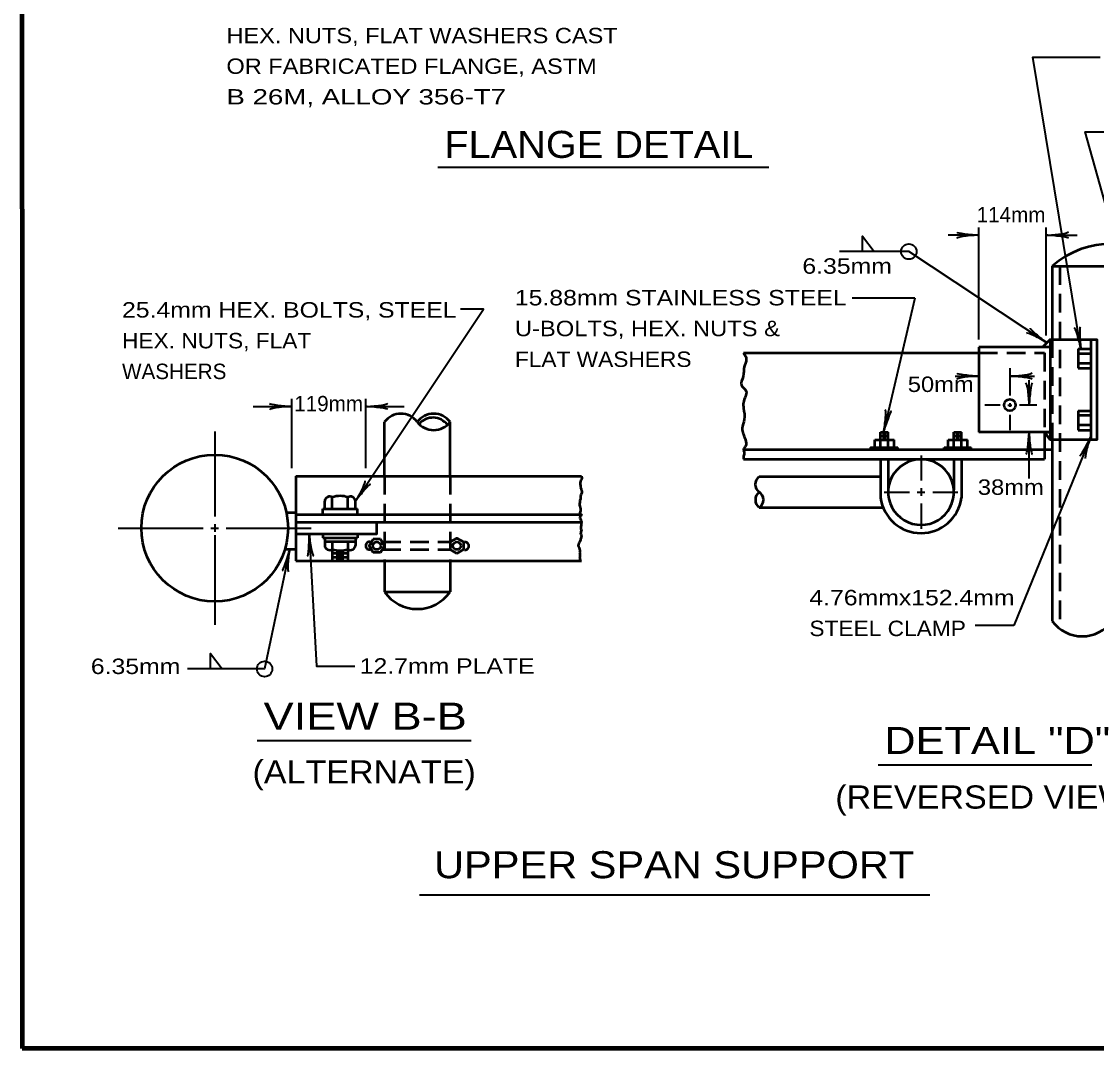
# Model space of a CAD drawing. Extents: x -29 to 827, y -14 to 530.
# Drawn here: x 28.3 to 196.8, y -2.8 to 158 of the extents above; entities that cross this region are included whole.
import ezdxf

# ---------------------------------------------------------------- set-up
doc = ezdxf.new("R2010")
doc.units = 0
doc.header["$LTSCALE"] = 0.97
doc.linetypes.add('MEDIUM_DASHED', pattern=[4.5, 3, -1.5])
doc.layers.add('1', color=7, linetype='Continuous', lineweight=53)

msp = doc.modelspace()

# ---------------------------------------------------------------- linework, layer by layer
at = {"layer": '1', "lineweight": 40}
for p, q in [((93.5745, 135.1797), (145.4625, 135.1797)), ((65.2914, 45.3846), (98.7954, 45.3846)), ((162.5634, 41.5926), (196.0674, 41.5926)), ((90.6859, 21.2275), (170.6693, 21.2275))]:
    msp.add_line(p, q, dxfattribs=at)
at = {"layer": '1', "lineweight": 35}
for p, q in [((178.3794, 108.2166), (178.3794, 125.7366)), ((188.9394, 108.8406), (188.9394, 125.7366)), ((178.3794, 124.5366), (173.5554, 124.5366)), ((188.9394, 124.5366), (193.7634, 124.5366)), ((167.4114, 121.9686), (156.5154, 121.9686)), ((189.0354, 107.6646), (167.4114, 121.9686)), ((168.3474, 114.6486), (158.4989, 114.6486)), ((168.3474, 114.6486), (163.4034, 93.6966)), ((183.2274, 103.6806), (183.2274, 99.4326)), ((174.6594, 102.4566), (178.3794, 102.4566)), ((183.2274, 102.4566), (187.0674, 102.4566)), ((186.2514, 97.9206), (186.2514, 101.8326)), ((70.7154, 88.0326), (70.7154, 98.9046)), ((82.2834, 88.0326), (82.2834, 98.9046)), ((181.7154, 97.9206), (179.2914, 97.9206)), ((182.9154, 97.9206), (183.5154, 97.9206)), ((183.2274, 98.2326), (183.2274, 97.6326)), ((187.4514, 97.9206), (184.7394, 97.9206)), ((64.6674, 97.7046), (70.7154, 97.7046)), ((82.2834, 97.7046), (88.3314, 97.7046)), ((183.2274, 96.4086), (183.2274, 93.9846)), ((58.6194, 93.7686), (58.6194, 80.4726)), ((195.9234, 93.0006), (183.8274, 63.4086)), ((186.2514, 86.4246), (186.2514, 93.6966)), ((169.3074, 90.0486), (169.3074, 86.1126)), ((163.5474, 84.2886), (167.5074, 84.2886)), ((168.7074, 84.2886), (169.9074, 84.2886)), ((169.3074, 84.8886), (169.3074, 83.6886)), ((171.1314, 84.2886), (175.0674, 84.2886)), ((169.3074, 82.4886), (169.3074, 78.5526)), ((43.4994, 78.6486), (56.7954, 78.6486)), ((58.0194, 78.6486), (58.6194, 78.6486)), ((58.6194, 78.6486), (58.6194, 78.0486)), ((58.6194, 77.5686), (58.6194, 63.5286)), ((60.4194, 78.6486), (73.7394, 78.6486)), ((183.8274, 63.4086), (177.7794, 63.4086))]:
    msp.add_line(p, q, dxfattribs=at)
at = {"layer": '1'}
for p, q in [((189.8754, 119.6886), (208.6194, 119.6886)), ((189.8754, 119.6886), (189.8754, 108.2166)), ((189.5634, 108.2166), (188.3634, 106.9926)), ((189.5634, 108.2166), (189.5634, 92.4726)), ((195.9234, 108.2166), (195.9234, 92.4726)), ((178.3794, 106.9926), (178.3794, 93.6966)), ((189.5634, 106.9926), (178.3794, 106.9926)), ((193.9554, 106.7046), (193.9554, 103.6806)), ((193.9554, 106.7046), (195.9234, 106.7046)), ((141.4914, 106.0806), (178.3794, 106.0806)), ((195.9234, 105.9366), (193.9554, 105.9366)), ((195.9234, 104.4246), (193.9554, 104.4246)), ((193.9554, 103.6806), (195.9234, 103.6806)), ((193.9554, 97.0086), (193.9554, 93.9846)), ((193.9554, 97.0086), (195.9234, 97.0086)), ((195.9234, 96.2646), (193.9554, 96.2646)), ((85.2354, 86.8086), (85.2354, 95.2806)), ((95.5074, 86.8086), (95.5074, 95.2806)), ((195.9234, 94.7526), (193.9554, 94.7526)), ((162.9714, 91.2726), (162.9714, 93.6966)), ((162.9714, 93.6966), (164.1714, 93.6966)), ((162.9714, 93.0966), (164.1714, 93.0966)), ((163.2594, 93.3846), (163.8594, 93.3846)), ((163.2594, 92.7846), (163.8594, 92.7846)), ((164.1714, 91.2726), (164.1714, 93.6966)), ((174.4434, 91.2726), (174.4434, 93.6966)), ((174.4434, 93.6966), (175.6674, 93.6966)), ((174.4434, 93.0966), (175.6674, 93.0966)), ((174.7554, 93.3846), (175.3554, 93.3846)), ((174.7554, 92.7846), (175.3554, 92.7846)), ((175.6674, 91.2726), (175.6674, 93.6966)), ((189.5634, 93.6966), (178.3794, 93.6966)), ((188.6754, 93.6966), (188.6754, 89.4486)), ((188.6754, 93.6966), (189.5634, 92.4726)), ((193.9554, 93.9846), (195.9234, 93.9846)), ((162.0594, 91.2726), (162.0594, 92.4726)), ((162.0594, 92.4726), (165.0834, 92.4726)), ((165.0834, 91.2726), (165.0834, 92.4726)), ((165.6834, 90.9606), (165.6834, 91.2726)), ((172.9314, 90.9606), (172.9314, 91.2726)), ((172.9314, 91.2726), (177.1794, 91.2726)), ((173.5554, 91.2726), (173.5554, 92.4726)), ((173.5554, 92.4726), (176.5794, 92.4726)), ((176.5794, 91.2726), (176.5794, 92.4726)), ((177.1794, 90.9606), (177.1794, 91.2726)), ((189.8754, 92.4726), (189.8754, 64.0566)), ((141.4914, 90.9606), (189.8754, 90.9606)), ((162.9714, 89.4486), (162.9714, 83.4006)), ((164.1714, 89.4486), (164.1714, 84.6246)), ((174.4434, 89.4486), (174.4434, 84.6246)), ((175.6674, 89.4486), (175.6674, 83.4006)), ((71.3154, 86.8086), (116.0754, 86.8086)), ((71.3154, 86.8086), (71.3154, 73.5126)), ((143.9154, 86.7126), (162.9714, 86.7126)), ((75.8514, 81.6726), (75.8514, 82.8966)), ((77.0514, 81.6726), (77.0514, 83.4966)), ((79.4754, 81.6726), (79.4754, 83.4966)), ((80.6994, 81.6726), (80.6994, 82.8966)), ((69.8514, 81.0726), (71.3154, 81.0726)), ((75.5394, 80.7606), (75.5394, 81.6726)), ((75.5394, 81.6726), (80.9874, 81.6726)), ((80.9874, 80.7606), (80.9874, 81.6726)), ((143.9154, 81.8646), (163.3794, 81.8646)), ((71.3154, 80.7606), (116.0754, 80.7606)), ((71.3154, 79.5606), (116.0754, 79.5606)), ((75.5394, 77.7366), (75.5394, 77.1366)), ((80.9874, 77.7366), (80.9874, 77.1366)), ((75.5394, 77.1366), (80.9874, 77.1366)), ((75.8514, 77.1366), (75.8514, 75.9366)), ((75.8514, 76.5366), (80.6994, 76.5366)), ((77.0514, 76.5366), (77.0514, 73.5126)), ((79.4754, 76.5366), (79.4754, 73.5126)), ((80.6994, 77.1366), (80.6994, 75.9366)), ((84.6114, 76.9446), (83.4354, 76.9446)), ((95.5074, 76.4886), (95.5074, 75.2886)), ((97.6194, 76.4886), (97.6194, 75.2886)), ((69.6114, 75.3366), (71.3154, 75.3366)), ((77.0514, 74.7126), (79.4754, 74.7126)), ((77.6754, 75.0246), (78.8754, 75.0246)), ((77.6754, 74.4246), (78.8754, 74.4246)), ((84.6114, 74.8326), (83.4354, 74.8326)), ((96.5634, 74.6886), (95.5074, 75.2886)), ((97.6194, 75.2886), (96.5634, 74.6886)), ((71.3154, 73.5126), (116.0754, 73.5126)), ((77.0514, 74.1126), (79.4754, 74.1126)), ((77.6754, 73.8246), (78.8754, 73.8246)), ((85.2354, 73.5126), (85.2354, 68.6646)), ((95.5074, 73.5126), (95.5074, 68.6646)), ((85.2354, 68.6646), (95.5074, 68.6646))]:
    msp.add_line(p, q, dxfattribs=at)
at = {"layer": '1', "linetype": 'MEDIUM_DASHED'}
for p, q in [((191.0754, 119.6886), (191.0754, 62.8566)), ((189.8754, 108.2166), (189.8754, 92.4726)), ((85.2354, 86.8086), (85.2354, 73.5126)), ((95.5074, 86.8086), (95.5074, 73.5126)), ((84.8754, 76.4886), (95.5074, 76.4886)), ((84.8754, 75.2886), (95.5074, 75.2886))]:
    msp.add_line(p, q, dxfattribs=at)
at = {"layer": '1', "lineweight": 158}
msp.add_line((820.0407, -2.8455), (28.4407, -2.8455), dxfattribs=at)
msp.add_lwpolyline([(820.0407, 523.2545), (28.3407, 523.1545), (28.4407, -2.8455)], dxfattribs=at)
at = {"layer": '1', "lineweight": 35}
for points in [[(194.3533, 106.7046), (186.8294, 152.4004), (197.3654, 152.4004)], [(203.1234, 111.8406), (195.0114, 140.7126), (205.5474, 140.7126)], [(160.1394, 121.9686), (160.1394, 124.3686), (161.9634, 121.9686)], [(80.6994, 82.8966), (100.7394, 112.9446), (97.1522, 112.9446)], [(58.6194, 79.2486), (58.6194, 78.6486), (59.2194, 78.6486)], [(73.4274, 77.7366), (74.5554, 57.0246), (80.6034, 57.0246)], [(70.3794, 75.3366), (66.4434, 56.5926), (54.3474, 56.5926)], [(57.9714, 56.5926), (57.9714, 59.0166), (59.7714, 56.5926)]]:
    msp.add_lwpolyline(points, dxfattribs=at)
at = {"layer": '1'}
for points in [[(188.3634, 106.9926), (189.5634, 108.2166), (189.5634, 106.9926)], [(189.5634, 92.4726), (188.6754, 93.6966), (189.5634, 93.6966)]]:
    msp.add_lwpolyline(points, close=True, dxfattribs=at)
for points in [[(189.5634, 108.2166), (196.8354, 108.2166), (196.8354, 92.4726), (189.5634, 92.4726)], [(161.4594, 90.9606), (161.4594, 91.2726), (165.6834, 91.2726)], [(141.4914, 89.4486), (164.1714, 89.4486), (174.4434, 89.4486), (188.6754, 89.4486)], [(71.3154, 77.7366), (84.0114, 77.7366), (84.0114, 79.5606)], [(83.4354, 74.8326), (82.8114, 75.8886), (83.4354, 76.9446)], [(84.6114, 76.9446), (85.2354, 75.8886), (84.6114, 74.8326)], [(95.5074, 76.4886), (96.5634, 77.0886), (97.6194, 76.4886)]]:
    msp.add_lwpolyline(points, dxfattribs=at)
at = {"layer": '1', "linetype": 'MEDIUM_DASHED'}
msp.add_lwpolyline([(178.3794, 106.0806), (188.6754, 106.0806), (188.6754, 93.6966)], dxfattribs=at)
at = {"layer": '1', "lineweight": 35}
for centre in [(167.4011, 121.9584), (66.4358, 56.5906)]:
    msp.add_circle(centre, 1.2096, dxfattribs=at)
at = {"layer": '1'}
for centre, radius in [((183.2249, 97.9252), 0.9072), ((58.6144, 78.6518), 11.4912), ((84.023, 75.8857), 0.6048), ((96.5656, 75.8857), 0.6048)]:
    msp.add_circle(centre, radius, dxfattribs=at)
for centre, radius, start, end in [((199.2521, 108.8867), 14.3095, 49.07159, 130.92841), ((87.796, 93.3356), 3.2253, 37.16004, 142.83996), ((92.9368, 93.3356), 3.2253, 37.16004, 142.83996), ((92.9368, 97.2321), 3.2253, 217.16004, 322.83996), ((92.831, 93.1726), 2.7851, 36.24736, 140.76859), ((169.3145, 84.2854), 5.1509, 356.40861, 183.59139), ((144.8528, 85.5008), 1.5318, 127.84869, 232.15131), ((144.91, 83.0816), 1.5676, 129.50016, 230.49985), ((143.1247, 83.0816), 1.4728, 304.78683, 56.54264), ((169.3145, 84.2969), 5.1509, 176.40861, 3.59139), ((76.6486, 82.8026), 0.8017, 59.06287, 174.06723), ((78.2704, 79.9306), 3.7595, 71.23152, 108.76847), ((79.8921, 82.8026), 0.8017, 5.93277, 120.93713), ((169.3145, 84.2729), 6.4088, 187.73761, 352.26239), ((76.6486, 76.0131), 0.8017, 185.93277, 300.93712), ((79.8921, 76.0131), 0.8017, 239.06287, 354.06723), ((82.8801, 75.8857), 0.6024, 82.89428, 277.10571), ((97.8541, 75.8598), 0.6024, 262.89429, 97.10572), ((78.2704, 78.885), 3.7595, 251.23153, 288.76848), ((90.3664, 72.2544), 6.2656, 214.86649, 325.13351), ((194.5649, 67.5743), 5.8605, 216.88967, 323.11034)]:
    msp.add_arc(centre, radius, start, end, dxfattribs=at)
at = {"layer": '1', "lineweight": 40}
for centre, major_axis, ratio, start_param, end_param in [((177.0312, 124.7923), (2.1246, -0.2125), 0.07063, 3.14071475, 5.41810995), ((190.2518, 124.8706), (-2.16, -0.1889), 0.122415, 0.89635335, 3.14159265), ((190.2518, 124.8706), (-2.16, -0.1889), 0.122415, 0.89635335, 3.14159265), ((177.0666, 124.2022), (2.16, 0.1889), 0.122415, 0.89635335, 3.14159265), ((190.2873, 124.2804), (-2.1246, 0.2125), 0.07063, 3.14071475, 5.41810995), ((190.2873, 124.2804), (-2.1246, 0.2125), 0.07063, 3.14071475, 5.41810995), ((188.0503, 108.6322), (-1.656, 1.3479), 0.07063, 6.28230741, 8.55970261), ((193.8134, 107.9428), (0.533, -2.0839), 0.122415, 0.89635335, 3.14159265), ((194.3854, 108.0726), (0.1345, -2.114), 0.07063, 3.14071475, 5.41810995), ((187.7547, 108.1202), (1.9066, -1.0325), 0.122415, 0.89635335, 3.14159265), ((177.0312, 102.7171), (2.1246, -0.2125), 0.07063, 3.14071475, 5.41810995), ((184.5448, 102.7954), (-2.16, -0.1889), 0.122415, 0.89635335, 3.14159265), ((184.5448, 102.7954), (-2.16, -0.1889), 0.122415, 0.89635335, 3.14159265), ((177.0666, 102.127), (2.16, 0.1889), 0.122415, 0.89635335, 3.14159265), ((184.5803, 102.2052), (-2.1246, 0.2125), 0.07063, 3.14071475, 5.41810995), ((184.5803, 102.2052), (-2.1246, 0.2125), 0.07063, 3.14071475, 5.41810995), ((185.9147, 99.2451), (0.1889, -2.16), 0.122415, 0.89635335, 3.14159265), ((186.5049, 99.2806), (-0.2125, -2.1246), 0.07063, 3.14071475, 5.41810995), ((69.3553, 97.959), (2.1246, -0.2125), 0.07063, 3.14071475, 5.41810995), ((69.3553, 97.959), (2.1246, -0.2125), 0.07063, 3.14071475, 5.41810995), ((83.6023, 98.0372), (-2.16, -0.1889), 0.122415, 0.89635335, 3.14159265), ((69.3907, 97.3688), (2.16, 0.1889), 0.122415, 0.89635335, 3.14159265), ((69.3907, 97.3688), (2.16, 0.1889), 0.122415, 0.89635335, 3.14159265), ((83.6377, 97.4471), (-2.1246, 0.2125), 0.07063, 3.14071475, 5.41810995), ((163.3889, 95.053), (-0.3112, -2.1458), 0.122415, 0.89635335, 3.14159265), ((163.9715, 94.9522), (0.6938, 2.0194), 0.07063, 6.28230741, 8.55970261), ((185.993, 92.3362), (0.2125, 2.1246), 0.07063, 3.14071475, 5.41810995), ((186.5831, 92.3717), (-0.1889, 2.16), 0.122415, 0.89635335, 3.14159265), ((195.1755, 91.8368), (-1.0013, -1.8859), 0.07063, 6.28230741, 8.55970261), ((195.7351, 91.6461), (0.6433, 2.0706), 0.122415, 0.89635335, 3.14159265), ((81.1441, 84.1689), (-1.0416, -1.9016), 0.122415, 0.89635335, 3.14159265), ((81.6547, 83.8708), (1.3559, 1.6495), 0.07063, 6.28230741, 8.55970261), ((73.2489, 76.3774), (-0.0965, -2.133), 0.07063, 6.28230741, 8.55970261), ((73.8362, 76.4449), (-0.3062, 2.1465), 0.122415, 0.89635335, 3.14159265), ((69.8529, 74.052), (-0.6459, -2.0352), 0.07063, 6.28230741, 8.55970261), ((70.4377, 73.965), (0.2605, 2.1525), 0.122415, 0.89635335, 3.14159265)]:
    msp.add_ellipse(centre, major_axis=major_axis, ratio=ratio, start_param=start_param, end_param=end_param, dxfattribs=at)
at = {"layer": '1'}
for points in [[(141.4914, 106.0806), (141.9234, 105.0726), (141.5874, 103.9206), (141.4434, 102.4086), (141.1554, 101.0166), (141.8994, 100.1046), (141.8034, 99.2886), (141.4674, 98.3046), (141.4914, 97.4406), (141.6114, 95.6646), (141.2754, 94.2726), (141.4434, 93.4326), (141.7794, 92.4726), (141.8034, 91.4886), (141.4914, 90.9606), (141.6114, 90.4086), (141.4674, 89.7606), (141.4914, 89.4486)], [(116.0754, 86.8086), (116.0994, 86.3286), (115.9794, 86.1366), (115.9074, 85.7766), (115.9314, 85.2966), (116.0274, 84.7686), (116.1474, 84.2886), (116.0994, 84.0486), (115.9554, 83.6406), (115.9554, 83.3766), (115.9314, 83.2326), (115.8354, 82.9686), (115.8114, 82.6566), (115.7874, 82.3926), (115.7874, 82.2486), (115.8834, 81.8886), (115.9554, 81.4806), (115.9074, 81.1926), (115.8594, 80.9526), (116.0754, 80.7606), (115.8354, 80.3046), (115.8834, 80.1606), (116.0034, 79.9926), (116.0034, 79.8246), (116.0754, 79.6086), (116.0754, 79.5606), (115.9794, 78.6246), (115.9794, 78.5526), (116.0754, 78.2646), (116.0034, 78.0486), (115.9554, 77.8566), (116.0274, 77.5926), (116.0754, 77.3766), (115.9554, 76.9446), (115.8834, 76.6566), (115.6914, 76.2726), (115.5954, 75.9126), (115.7154, 75.5526), (115.8114, 75.1206), (115.8114, 74.9526), (115.8114, 74.7126), (115.8354, 74.4006), (115.8114, 74.2086), (115.8114, 74.0406), (115.8354, 73.8246), (115.8114, 73.6566), (116.0754, 73.5126)]]:
    msp.add_spline(points, degree=3, dxfattribs=at)

# ---------------------------------------------------------------- texts
for s, height, width, p in [('HEX. NUTS, FLAT WASHERS CAST', 2.4, 1.15, (60.4538, 154.5991)), ('OR FABRICATED FLANGE, ASTM', 2.4, 1.15, (60.4538, 149.7991)), ('B 26M, ALLOY 356-T7 ', 2.4, 1.35, (60.4538, 144.9991)), ('FLANGE DETAIL', 4.234, 1.1, (94.5923, 136.634)), ('6.35mm', 2.419, 1.2, (150.7135, 118.4908)), ('15.88mm STAINLESS STEEL', 2.419, 1.2, (105.6583, 113.5317)), ('25.4mm HEX. BOLTS, STEEL', 2.419, 1.2, (44.0958, 111.6246)), ('U-BOLTS, HEX. NUTS &', 2.419, 1.15, (105.6583, 108.7125)), ('HEX. NUTS, FLAT', 2.419, 1.1, (44.0958, 106.8054)), ('FLAT WASHERS', 2.419, 1.1, (105.6583, 103.8933)), ('50mm', 2.419, 1.15, (167.2271, 99.9726)), ('38mm', 2.419, 1.15, (178.2102, 83.8638)), ('4.76mmx152.4mm', 2.419, 1.2, (151.8114, 66.5574)), ('STEEL CLAMP', 2.419, 1.1, (151.8114, 61.7382)), ('6.35mm', 2.419, 1.2, (39.2083, 55.7982)), ('12.7mm PLATE', 2.419, 1.2, (81.3474, 55.8486)), ('VIEW B-B', 4.234, 1.25, (66.2754, 47.0886)), ('DETAIL "D"', 4.234, 1.2, (163.5474, 43.2726)), ('(ALTERNATE)', 3.629, 1.1, (64.539, 38.6644)), ('(REVERSED VIEW)', 3.629, 1.1, (155.8712, 34.7247)), ('UPPER SPAN SUPPORT', 4.234, 1.15, (92.9899, 23.8195))]:
    msp.add_text(s, height=height, dxfattribs=dict(at, width=width)).set_placement(p)
for s, p in [('114mm', (178.0222, 126.5214)), ('WASHERS', (44.0958, 101.9862)), ('119mm', (71.0779, 96.9414))]:
    msp.add_text(s, height=2.419, dxfattribs=at).set_placement(p)

doc.saveas('drawing.dxf')
